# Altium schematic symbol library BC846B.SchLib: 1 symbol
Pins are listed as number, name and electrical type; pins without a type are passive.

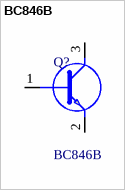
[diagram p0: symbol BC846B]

## BC846B
designator Q?
Bipolar Transistors - BJT Bipolar Transistor, SOT-23, 65V, 100mA, NPN; Manufacturer_Name: Diotec; Geometry.Height: 1.1mm
footprint SOT95P230X110-3N
pins: 1 B, 2 E, 3 C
